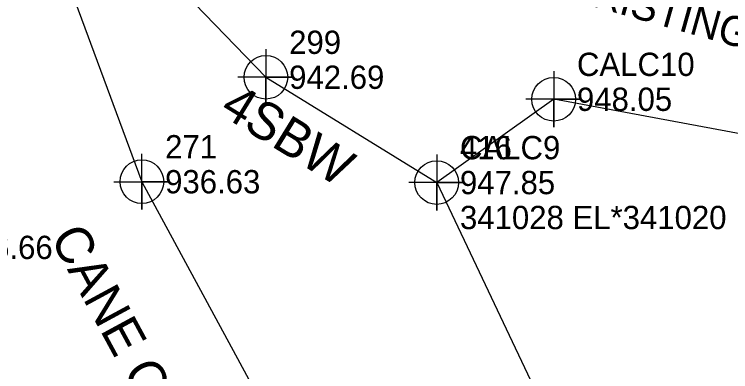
# Model space of a CAD drawing. Extents: x 1150279 to 1151282, y 654632 to 657999.
# Drawn here: x 1150767.1 to 1150844, y 657071.3 to 657109.7 of the extents above; entities that cross this region are included whole.
import ezdxf

# ---------------------------------------------------------------- set-up
doc = ezdxf.new("R2010")
doc.units = 0
for name, color, linetype in [('Exist Hydro Jurisdictional Stream or Body of Water', 7, 'Continuous'), ('Exist Hydro Jurisdictional Stream or Body of Water Text', 7, 'Continuous'), ('Exist Hydro Stream or Body of Water Cogo Elevation', 7, 'Continuous'), ('Exist Hydro Stream or Body of Water Cogo Number', 7, 'Continuous'), ('Exist Hydro Stream or Body of Water Cogo Point CELL', 7, 'Continuous'), ('Exist Other Culture Fence Line', 7, 'Continuous'), ('Exist Other Culture Fence Line Cogo Comment', 7, 'Continuous'), ('Exist Other Culture Fence Line Cogo Elevation', 7, 'Continuous'), ('Exist Other Culture Fence Line Cogo Number', 7, 'Continuous'), ('Exist Other Culture Fence Line Cogo Point CELL', 7, 'Continuous'), ('Exist Other Culture Fence Line Text', 7, 'Continuous'), ('Exist Right of Way Line', 7, 'Continuous'), ('Exist Right of Way Line Text', 7, 'Continuous')]:
    doc.layers.add(name, color=color, linetype=linetype)

msp = doc.modelspace()

# ---------------------------------------------------------------- linework, layer by layer
at = {"layer": 'Exist Hydro Jurisdictional Stream or Body of Water'}
msp.add_lwpolyline([(1150769.348, 657125.308), (1150769.521, 657122.143), (1150780.786, 657091.685), (1150798.339, 657059.295), (1150820.355, 657029.39), (1150829.476, 657003.097)], dxfattribs=at)
at = {"layer": 'Exist Hydro Stream or Body of Water Cogo Point CELL'}
msp.add_lwpolyline([(1150777.786, 657091.685), (1150783.786, 657091.685), (1150780.786, 657091.685), (1150780.786, 657088.685), (1150780.786, 657094.685)], dxfattribs=at)
msp.add_circle((1150780.786, 657091.685), 2.344, dxfattribs=at)
at = {"layer": 'Exist Other Culture Fence Line'}
for points in [[(1150773.321, 657124.389), (1150794.109, 657102.9), (1150812.457, 657091.594)], [(1151064.379, 657042.204), (1151035.792, 657039.664), (1150986.531, 657050.151), (1150941.416, 657063.204), (1150898.391, 657078.653), (1150854.858, 657094.995), (1150825.025, 657100.534), (1150812.457, 657091.594), (1150835.172, 657043.741), (1150852.719, 657007.431)]]:
    msp.add_lwpolyline(points, dxfattribs=at)
at = {"layer": 'Exist Other Culture Fence Line Cogo Point CELL'}
for points in [[(1150794.109, 657105.9), (1150794.109, 657099.9), (1150794.109, 657102.9), (1150797.109, 657102.9), (1150791.109, 657102.9)], [(1150825.025, 657103.534), (1150825.025, 657097.534), (1150825.025, 657100.534), (1150828.025, 657100.534), (1150822.025, 657100.534)], [(1150812.457, 657094.594), (1150812.457, 657088.594), (1150812.457, 657091.594), (1150815.457, 657091.594), (1150809.457, 657091.594)], [(1150812.457, 657094.594), (1150812.457, 657088.594), (1150812.457, 657091.594), (1150815.457, 657091.594), (1150809.457, 657091.594)]]:
    msp.add_lwpolyline(points, dxfattribs=at)
for centre in [(1150794.109, 657102.9), (1150825.025, 657100.534), (1150812.457, 657091.594), (1150812.457, 657091.594)]:
    msp.add_circle(centre, 2.344, dxfattribs=at)
at = {"layer": 'Exist Right of Way Line'}
msp.add_arc((1150793.42, 656935.454), 183, 65.68044, 91.66254, dxfattribs=at)

# ---------------------------------------------------------------- texts
at = {"layer": 'Exist Hydro Jurisdictional Stream or Body of Water Text'}
msp.add_text('CANE CREEK', height=4, rotation=298.45461, dxfattribs=at).set_placement((1150770.87, 657085.692))
at = {"layer": 'Exist Hydro Stream or Body of Water Cogo Elevation'}
for s, p in [('936.63', (1150783.286, 657090.435)), ('936.66', (1150760.985, 657083.386))]:
    msp.add_text(s, height=2.5, dxfattribs=at).set_placement(p)
at = {"layer": 'Exist Hydro Stream or Body of Water Cogo Number'}
msp.add_text('271', height=2.5, dxfattribs=at).set_placement((1150783.286, 657094.185))
at = {"layer": 'Exist Other Culture Fence Line Cogo Comment'}
msp.add_text('341028 EL*341020', height=2.5, dxfattribs=at).set_placement((1150814.957, 657086.594))
at = {"layer": 'Exist Other Culture Fence Line Cogo Elevation'}
for s, p in [('942.69', (1150796.609, 657101.65)), ('948.05', (1150827.525, 657099.284)), ('947.85', (1150814.957, 657090.344)), ('947.85', (1150814.957, 657090.344))]:
    msp.add_text(s, height=2.5, dxfattribs=at).set_placement(p)
at = {"layer": 'Exist Other Culture Fence Line Cogo Number'}
for s, p in [('299', (1150796.609, 657105.4)), ('CALC10', (1150827.525, 657103.034)), ('416', (1150814.957, 657094.094)), ('CALC9', (1150814.957, 657094.094))]:
    msp.add_text(s, height=2.5, dxfattribs=at).set_placement(p)
at = {"layer": 'Exist Other Culture Fence Line Text'}
msp.add_text('4SBW', height=4, rotation=328.35803, dxfattribs=at).set_placement((1150788.996, 657099.003))
at = {"layer": 'Exist Right of Way Line Text'}
msp.add_text('EXISTING R/W', height=3.2, rotation=344.27394, dxfattribs=at).set_placement((1150826.415, 657111.293))

doc.saveas('drawing.dxf')
